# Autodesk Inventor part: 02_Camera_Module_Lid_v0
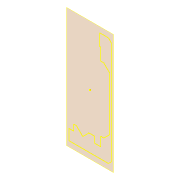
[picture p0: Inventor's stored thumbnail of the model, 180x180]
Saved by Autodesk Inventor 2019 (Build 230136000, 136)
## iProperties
Created: 2021-09
Part Number: 02_Camera_Module_Lid_v0
Material: Generisch
Document SubType Name: Modeling
Designer: Muriel
Density: 1 g/cm^3
Appearance: Vorgabe
Author: Muriel
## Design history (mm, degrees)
workplane "Arbeitsebene1"
sketch "Skizze1"
  geometry: L1 (6, 17.9)-(7, 16.9) reference; L2 (3.1, 17.9)-(6, 17.9) reference; L3 (3.1, 14)-(3.1, 17.9) reference; L4 (3.5, 14)-(3.1, 14) reference; L5 (3.5, 10)-(3.5, 14) reference; L6 (4.5, 10)-(3.5, 10) reference; L7 (6.4, 8.1)-(4.5, 10) reference; L8 (6.4, -9.5)-(6.4, 8.1) reference; L9 (4.5, -11.4)-(6.4, -9.5) reference; L10 (3.5, -11.4)-(4.5, -11.4) reference; L11 (3.5, -14.4)-(3.5, -11.4) reference; L12 (1.5, -14.4)-(3.5, -14.4) reference; L13 (1.5, -12.4)-(1.5, -14.4) reference; L14 (-0.5, -12.4)-(1.5, -12.4) reference; L15 (-0.5, -12.5)-(-0.5, -12.4) reference; L16 (-2.4, -14.4)-(-0.5, -12.5) reference; L17 (-2.5, -14.4)-(-2.4, -14.4) reference; L18 (-4.4, -12.5)-(-2.5, -14.4) reference; L19 (-4.4, -12.4)-(-4.4, -12.5) reference; L20 (-5.4, -12.4)-(-4.4, -12.4) reference; L21 (-5.4, -14.4)-(-5.4, -12.4) reference; L22 (-6.9, -14.4)-(-5.4, -14.4) reference; L23 (-6.9, -17.9)-(-6.9, -14.4) reference; L24 (6, -17.9)-(-6.9, -17.9) reference; L25 (7, -16.9)-(6, -17.9) reference; L26 (7, 16.9)-(7, -16.9) reference; L27 (6, 17.9)-(7, 16.9) reference; L28 (3.1, 17.9)-(6, 17.9) reference; L29 (3.1, 14)-(3.1, 17.9) reference; L30 (3.5, 14)-(3.1, 14) reference; L31 (3.5, 10)-(3.5, 14) reference; L32 (4.5, 10)-(3.5, 10) reference; L33 (6.4, 8.1)-(4.5, 10) reference; L34 (6.4, -9.5)-(6.4, 8.1) reference; L35 (4.5, -11.4)-(6.4, -9.5) reference; L36 (3.5, -11.4)-(4.5, -11.4) reference; L37 (3.5, -14.4)-(3.5, -11.4) reference; L38 (1.5, -14.4)-(3.5, -14.4) reference; L39 (1.5, -12.4)-(1.5, -14.4) reference; L40 (-0.5, -12.4)-(1.5, -12.4) reference; L41 (-0.5, -12.5)-(-0.5, -12.4) reference; L42 (-2.4, -14.4)-(-0.5, -12.5) reference; L43 (-2.5, -14.4)-(-2.4, -14.4) reference; L44 (-4.4, -12.5)-(-2.5, -14.4) reference; L45 (-4.4, -12.4)-(-4.4, -12.5) reference; L46 (-5.4, -12.4)-(-4.4, -12.4) reference; L47 (-5.4, -14.4)-(-5.4, -12.4) reference; L48 (-6.9, -14.4)-(-5.4, -14.4) reference; L49 (-6.9, -17.9)-(-6.9, -14.4) reference; L50 (6, -17.9)-(-6.9, -17.9) reference; L51 (7, -16.9)-(6, -17.9) reference; L52 (7, 16.9)-(7, -16.9) reference; L53 (-9.8, -17.9)-(-10.8, -16.9) reference; L54 (-6.9, -17.9)-(-9.8, -17.9) reference; L55 (-6.9, -14)-(-6.9, -17.9) reference; L56 (-7.3, -14)-(-6.9, -14) reference; L57 (-7.3, -10)-(-7.3, -14) reference; L58 (-8.3, -10)-(-7.3, -10) reference; L59 (-10.2, -8.1)-(-8.3, -10) reference; L60 (-10.2, 9.5)-(-10.2, -8.1) reference; L61 (-8.3, 11.4)-(-10.2, 9.5) reference; L62 (-7.3, 11.4)-(-8.3, 11.4) reference; L63 (-7.3, 14.4)-(-7.3, 11.4) reference; L64 (-5.3, 14.4)-(-7.3, 14.4) reference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; C1 r 1.4 at (-3.9, -15.8) reference; C2 r 1.4 at (4.9, -15.8) reference; C3 r 1.4 at (-3.9, -15.8) reference; C4 r 1.4 at (4.9, -15.8) reference; C5 r 1.4 at (0.1, 15.8) reference; C6 r 1.4 at (-8.7, 15.8) reference; A1 r 1 centre (5.1, -3.25) between (5.1, -4.25) and (6.1, -3.25) reference; A2 r 1 centre (5.1, 2.25) between (6.1, 2.25) and (5.1, 3.25) reference; A3 r 1 centre (-8.9, 3.25) between (-8.9, 4.25) and (-9.9, 3.25) reference; A4 r 1 centre (-8.9, -2.25) between (-9.9, -2.25) and (-8.9, -3.25) reference; A5 r 1.3 centre (5.1, 2.25) between (6.4, 2.25) and (5.1, 3.55); A6 r 1.3 centre (5.1, -3.25) between (5.1, -4.55) and (6.4, -3.25); A7 r 1.3 centre (-8.9, -2.25) between (-10.2, -2.25) and (-8.9, -3.55); A8 r 1.3 centre (-8.9, 3.25) between (-8.9, 4.55) and (-10.2, 3.25); 1 further point
  constraints: 16 end point, 8 point on circle, 4 centre point, 10 other
  dimensions: "d0" = 0.3 distance between parallel lines of L81 L87; "d1" = 0.3 radial gap between concentric circles of A4 A7
extrude "Extrusion1" new body sketch "Skizze1" distance "d2" = 3; taper "d3" = 0 deg
sketch "Skizze2"
  geometry: 1 further point
sketch "Skizze3"
  geometry: C1 r 1.4 at (-8.7, 15.8) reference; C2 r 1.4 at (0.1, 15.8) reference; C3 r 1.4 at (4.9, -15.8) reference; C4 r 1.4 at (-3.9, -15.8) reference; 2 further points
  constraints: 1 coincident
hole "Bohrung1" sketch "Skizze3" at (0.1, 15.8), (4.9, -15.8), (-3.9, -15.8), (-8.7, 15.8) diameter "d4" = 2.8; stored, may be unused: countersink angle "d8" = 90 deg, drill point angle "d10" = 118 deg; dims "d5" = 6, "d6" = 5.5, "d7" = 1, "d9" = 12
chamfer "Fase1" distance "d11" = 2; stored, may be unused: second distance "d12" = 2, angle "d13" = 45 deg
node "Volumenkörper1"
node "Referenz1"
node "Referenz2"
node "Referenz3"
node "Referenz4"
node "Referenz5"
node "Referenz6"
node "Referenz7"
node "Referenz8"
node "Referenz9"
